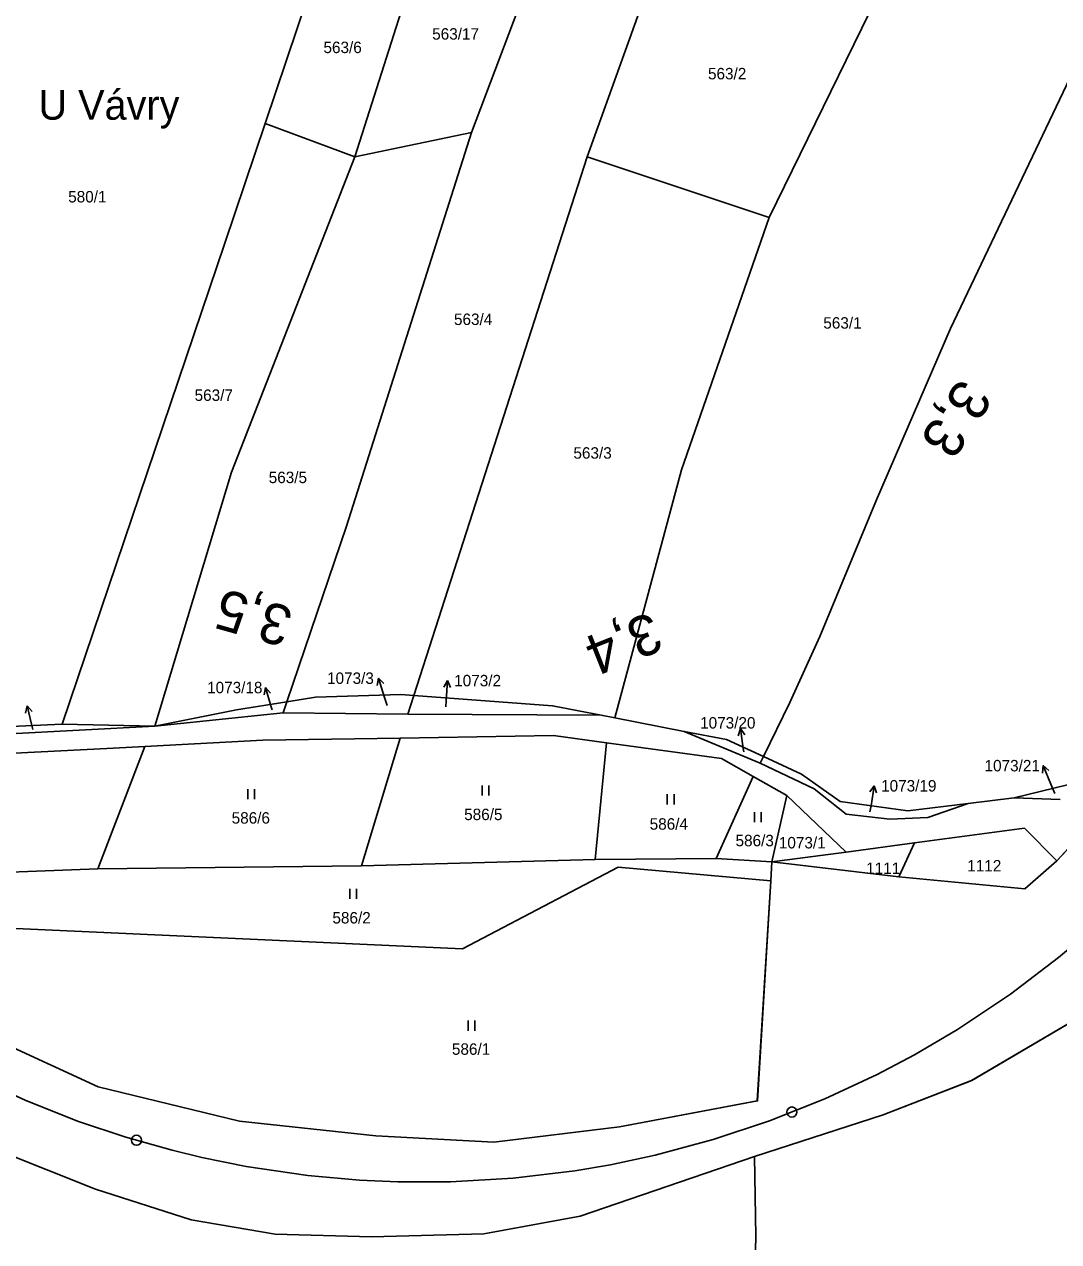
# Model space of a CAD drawing. Extents: x -738085 to -734306, y -1122197 to -1119753.
# Drawn here: x -736720.5 to -736566.9, y -1121765.8 to -1121585.1 of the extents above; entities that cross this region are included whole.
import ezdxf

# ---------------------------------------------------------------- set-up
doc = ezdxf.new("R2010")
doc.units = 0
for name, color, linetype in [('Hranice parcel', 7, 'Continuous'), ('Parcelní čísla', 7, 'Continuous'), ('Pop  PČ popisy', 7, 'Continuous'), ('Vrstva 1', 7, 'Continuous'), ('Vrstva 53', 7, 'Continuous'), ('Vrstva 7', 7, 'Continuous'), ('Značky kultur', 7, 'Continuous')]:
    doc.layers.add(name, color=color, linetype=linetype)

msp = doc.modelspace()

# ---------------------------------------------------------------- linework, layer by layer
at = {"layer": 'Hranice parcel'}
for p, q in [((-736641.3, -1121567.31), (-736654.1, -1121601.1)), ((-736587.35, -1121567.59), (-736609.89, -1121613.75)), ((-736671.39, -1121604.72), (-736661.23, -1121572.67)), ((-736684.73, -1121599.8), (-736676.26, -1121574.62)), ((-736684.73, -1121599.8), (-736671.39, -1121604.72)), ((-736654.1, -1121601.1), (-736671.39, -1121604.72)), ((-736636.93, -1121604.74), (-736662.64, -1121684.74)), ((-736636.93, -1121604.74), (-736609.89, -1121613.75)), ((-736681.48, -1121685.66), (-736682.04, -1121687.31)), ((-736662.64, -1121684.74), (-736663.52, -1121687.48)), ((-736682.04, -1121687.31), (-736701.11, -1121689.29)), ((-736682.04, -1121687.31), (-736663.52, -1121687.48)), ((-736736.91, -1121689.98), (-736714.87, -1121688.97)), ((-736701.11, -1121689.29), (-736714.87, -1121688.97)), ((-736663.52, -1121687.48), (-736634.85, -1121687.65)), ((-736632.82, -1121688.05), (-736634.85, -1121687.65)), ((-736622.51, -1121690.06), (-736632.82, -1121688.05)), ((-736664.68, -1121691.05), (-736670.41, -1121710.04)), ((-736611.23, -1121694.8), (-736622.51, -1121690.06)), ((-736702.57, -1121692.29), (-736709.58, -1121710.45)), ((-736634.04, -1121691.76), (-736635.7, -1121709.1)), ((-736610.75, -1121693.81), (-736611.23, -1121694.8)), ((-736612.26, -1121696.75), (-736617.75, -1121708.96)), ((-736612.26, -1121696.75), (-736607.27, -1121699.56)), ((-736563.59, -1121697.48), (-736573.53, -1121699.94)), ((-736607.27, -1121699.56), (-736609.49, -1121709.44)), ((-736598.47, -1121707.98), (-736607.27, -1121699.56)), ((-736573.53, -1121699.94), (-736580.32, -1121700.76)), ((-736566.66, -1121700.19), (-736573.53, -1121699.94)), ((-736561.91, -1121703.6), (-736567.16, -1121709.27)), ((-736588.33, -1121706.63), (-736598.47, -1121707.98)), ((-736590.63, -1121711.66), (-736588.33, -1121706.63)), ((-736635.7, -1121709.1), (-736670.41, -1121710.04)), ((-736617.75, -1121708.96), (-736635.7, -1121709.1)), ((-736609.49, -1121709.44), (-736617.75, -1121708.96)), ((-736598.47, -1121707.98), (-736609.49, -1121709.44)), ((-736670.41, -1121710.04), (-736709.58, -1121710.45)), ((-736609.49, -1121709.44), (-736609.66, -1121712.27)), ((-736590.63, -1121711.66), (-736609.49, -1121709.44))]:
    msp.add_line(p, q, dxfattribs=at)
for points in [[(-736624.69, -1121570.89), (-736629.45, -1121583.94), (-736636.93, -1121604.74)], [(-736610.75, -1121693.81), (-736606.84, -1121685.76), (-736602.37, -1121675.96), (-736593.95, -1121655.67), (-736582.95, -1121630.21), (-736556.62, -1121574.94)], [(-736714.87, -1121688.97), (-736690.71, -1121617.55), (-736684.73, -1121599.8)], [(-736654.1, -1121601.1), (-736672.66, -1121659.6), (-736681.48, -1121685.66)], [(-736671.39, -1121604.72), (-736689.72, -1121651.54), (-736701.11, -1121689.29)], [(-736609.89, -1121613.75), (-736622.89, -1121651.22), (-736632.82, -1121688.05)], [(-736681.48, -1121685.66), (-736688.98, -1121686.87), (-736701.11, -1121689.29)], [(-736662.64, -1121684.74), (-736664.57, -1121684.6), (-736677.23, -1121684.98), (-736681.48, -1121685.66)], [(-736634.85, -1121687.65), (-736642.05, -1121686.25), (-736662.64, -1121684.74)], [(-736701.11, -1121689.29), (-736723.58, -1121690.47), (-736736.91, -1121689.98)], [(-736702.57, -1121692.29), (-736685.04, -1121691.38), (-736664.68, -1121691.05)], [(-736664.68, -1121691.05), (-736641.9, -1121690.68), (-736634.04, -1121691.76)], [(-736610.75, -1121693.81), (-736616.22, -1121691.29), (-736622.51, -1121690.06)], [(-736738.53, -1121694.16), (-736708.22, -1121692.59), (-736702.57, -1121692.29)], [(-736634.04, -1121691.76), (-736616.97, -1121694.09), (-736612.26, -1121696.75)], [(-736580.32, -1121700.76), (-736589.3, -1121701.84), (-736599.36, -1121700.45), (-736605.08, -1121696.41), (-736610.75, -1121693.81)], [(-736580.32, -1121700.76), (-736586.32, -1121702.83), (-736591.96, -1121703.1), (-736598.48, -1121702.37), (-736603.22, -1121698.57), (-736611.23, -1121694.8)], [(-736567.16, -1121709.27), (-736571.99, -1121704.45), (-736588.33, -1121706.63)], [(-736709.58, -1121710.45), (-736756.42, -1121712.25), (-736761.9, -1121712.81)], [(-736609.66, -1121712.27), (-736632.32, -1121710.21), (-736655.43, -1121722.35), (-736721.72, -1121719.32), (-736729.67, -1121727.41), (-736731.16, -1121732.89)], [(-736567.16, -1121709.27), (-736571.91, -1121713.45), (-736590.63, -1121711.66)], [(-736609.66, -1121712.27), (-736611.62, -1121744.93), (-736632.11, -1121748.77), (-736650.76, -1121751.05), (-736668.27, -1121750.12), (-736688.52, -1121747.94), (-736709.5, -1121742.83), (-736731.16, -1121732.89)], [(-736612.06, -1121753.19), (-736592.94, -1121747.03), (-736579.82, -1121741.91), (-736552.55, -1121725.89)], [(-736734.55, -1121746.43), (-736724.6, -1121752.2), (-736709.93, -1121758.04), (-736695.7, -1121762.6), (-736683.21, -1121764.75), (-736668.91, -1121765.12), (-736652.26, -1121764.66), (-736637.94, -1121762.04), (-736612.06, -1121753.19)], [(-736612.06, -1121753.19), (-736611.88, -1121765.01), (-736612.41, -1121788.56), (-736616.6, -1121809.29)]]:
    msp.add_lwpolyline(points, dxfattribs=at)
at = {"layer": 'Pop  PČ popisy'}
for p, q in [((-736684.66, -1121683.54), (-736684.86, -1121684.65)), ((-736683.83, -1121686.43), (-736684.66, -1121683.54)), ((-736684.66, -1121683.54), (-736683.9, -1121684.37)), ((-736667.91, -1121682.16), (-736668.07, -1121683.26)), ((-736666.98, -1121685.01), (-736667.91, -1121682.16)), ((-736667.91, -1121682.16), (-736667.12, -1121682.95)), ((-736657.63, -1121682.52), (-736658.2, -1121683.48)), ((-736657.84, -1121685.51), (-736657.63, -1121682.52)), ((-736657.63, -1121682.52), (-736657.2, -1121683.55)), ((-736666.59, -1121686.21), (-736666.98, -1121685.01)), ((-736657.89, -1121686.39), (-736657.84, -1121685.51)), ((-736720.05, -1121686.26), (-736720.31, -1121687.34)), ((-736719.37, -1121689.18), (-736720.05, -1121686.26)), ((-736720.05, -1121686.26), (-736719.33, -1121687.12)), ((-736683.7, -1121686.88), (-736683.83, -1121686.43)), ((-736719.23, -1121689.76), (-736719.37, -1121689.18)), ((-736614.16, -1121689.64), (-736614.51, -1121690.7)), ((-736613.74, -1121692.61), (-736614.16, -1121689.64)), ((-736614.16, -1121689.64), (-736613.52, -1121690.56)), ((-736613.67, -1121693.08), (-736613.74, -1121692.61)), ((-736569.23, -1121695.15), (-736569.3, -1121696.27)), ((-736568.06, -1121697.91), (-736569.23, -1121695.15)), ((-736569.23, -1121695.15), (-736568.38, -1121695.87)), ((-736594.29, -1121698.14), (-736594.94, -1121699.05)), ((-736594.76, -1121701.1), (-736594.29, -1121698.14)), ((-736594.29, -1121698.14), (-736593.95, -1121699.2)), ((-736567.47, -1121699.31), (-736568.06, -1121697.91)), ((-736594.92, -1121702.03), (-736594.76, -1121701.1))]:
    msp.add_line(p, q, dxfattribs=at)
at = {"layer": 'Vrstva 1'}
msp.add_lwpolyline([(-736563.11, -1121720.47), (-736566.92, -1121723.66), (-736574.05, -1121729.09), (-736581.91, -1121734.35), (-736588.31, -1121738.11), (-736593.86, -1121741.02), (-736601.6, -1121744.63), (-736609.85, -1121747.92), (-736618.18, -1121750.68), (-736626.81, -1121753), (-736633.46, -1121754.41), (-736638.73, -1121755.31), (-736647.92, -1121756.42), (-736657.2, -1121756.95), (-736665.04, -1121756.95), (-736670.71, -1121756.69), (-736678.37, -1121756.01), (-736687.55, -1121754.66), (-736694.14, -1121753.33), (-736698.54, -1121752.27), (-736705.39, -1121750.34), (-736712.58, -1121747.93), (-736720.34, -1121744.85), (-736726.52, -1121742.02)], dxfattribs=at)
at = {"layer": 'Vrstva 53'}
for points in [[(-736776.82, -1121696.15), (-736761.9, -1121712.81), (-736745.83, -1121726.21), (-736731.16, -1121732.89), (-736709.49, -1121742.83), (-736688.52, -1121747.94), (-736668.27, -1121750.12), (-736650.76, -1121751.05), (-736632.11, -1121748.77), (-736611.65, -1121744.93), (-736609.66, -1121712.27), (-736609.49, -1121709.44), (-736590.63, -1121711.66), (-736571.91, -1121713.45), (-736567.16, -1121709.27), (-736561.91, -1121703.6), (-736552.9, -1121693.88), (-736544.38, -1121684.19), (-736507.68, -1121632.57), (-736475.27, -1121586.19)], [(-736552.55, -1121725.89), (-736579.86, -1121741.91), (-736592.94, -1121747.03), (-736612.06, -1121753.19), (-736637.94, -1121762.04), (-736652.26, -1121764.66), (-736668.91, -1121765.12), (-736683.21, -1121764.75), (-736695.7, -1121762.6), (-736709.93, -1121758.04), (-736724.6, -1121752.2), (-736734.55, -1121746.43), (-736744.92, -1121740.07), (-736753.63, -1121733.84), (-736761.39, -1121727.01), (-736765.38, -1121723.5), (-736772.96, -1121714.48), (-736774.04, -1121713.02), (-736780.95, -1121704.53), (-736785.85, -1121697.11), (-736781.46, -1121696.64), (-736776.82, -1121696.15)]]:
    msp.add_lwpolyline(points, dxfattribs=at)
at = {"layer": 'Vrstva 7'}
for centre in [(-736606.51, -1121746.59), (-736703.82, -1121750.78)]:
    msp.add_circle(centre, 0.75, dxfattribs=at)
at = {"layer": 'Značky kultur'}
for p, q in [((-736652.52, -1121699.6), (-736652.52, -1121698.1)), ((-736651.52, -1121699.6), (-736651.52, -1121698.1)), ((-736687.3, -1121700.12), (-736687.3, -1121698.62)), ((-736686.3, -1121700.12), (-736686.3, -1121698.62)), ((-736625.01, -1121700.9), (-736625.01, -1121699.4)), ((-736624.01, -1121700.9), (-736624.01, -1121699.4)), ((-736612.08, -1121703.55), (-736612.08, -1121702.05)), ((-736611.08, -1121703.55), (-736611.08, -1121702.05)), ((-736672.14, -1121714.95), (-736672.14, -1121713.45)), ((-736671.14, -1121714.95), (-736671.14, -1121713.45)), ((-736654.6, -1121734.52), (-736654.6, -1121733.02)), ((-736653.6, -1121734.52), (-736653.6, -1121733.02))]:
    msp.add_line(p, q, dxfattribs=at)

# ---------------------------------------------------------------- texts
at = {"layer": 'Parcelní čísla'}
for s, p in [('563/17', (-736659.92, -1121587.33)), ('563/6', (-736676.06, -1121589.33)), ('563/2', (-736618.97, -1121593.23)), ('580/1', (-736713.96, -1121611.51)), ('563/4', (-736656.68, -1121629.71)), ('563/1', (-736601.85, -1121630.25)), ('563/7', (-736695.19, -1121640.98)), ('563/3', (-736638.95, -1121649.56)), ('563/5', (-736684.19, -1121653.19)), ('1073/3', (-736675.53, -1121683.01)), ('1073/2', (-736656.65, -1121683.37)), ('1073/18', (-736693.34, -1121684.4)), ('1073/20', (-736620.14, -1121689.64)), ('1073/21', (-736577.91, -1121696)), ('1073/19', (-736593.27, -1121698.99)), ('586/5', (-736655.17, -1121703.24)), ('586/6', (-736689.69, -1121703.76)), ('586/4', (-736627.63, -1121704.66)), ('586/3', (-736614.88, -1121707.12)), ('1073/1', (-736608.45, -1121707.44)), ('1112', (-736580.48, -1121710.86)), ('1111', (-736595.49, -1121711.24)), ('586/2', (-736674.73, -1121718.59)), ('586/1', (-736656.99, -1121738.09))]:
    msp.add_text(s, height=1.7, dxfattribs=at).set_placement(p)
at = {"layer": 'Pop  PČ popisy'}
msp.add_text('U Vávry', height=4.4, dxfattribs=at).set_placement((-736718.37, -1121599.22))
at = {"layer": 'Vrstva 7'}
for s, rotation, p in [('3,3', 237.0514, (-736581.55, -1121637.37)), ('3,5', 164.2393, (-736680.27, -1121671.84)), ('3,4', 201.7379, (-736627.41, -1121672.21))]:
    msp.add_text(s, height=6, rotation=rotation, dxfattribs=at).set_placement(p)

doc.saveas('drawing.dxf')
